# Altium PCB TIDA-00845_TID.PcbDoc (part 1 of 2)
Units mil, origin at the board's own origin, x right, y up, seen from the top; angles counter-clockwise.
Board outline 5936.8 x 4260 mil, 4 copper layers (Top Layer, Layer 2, Layer 3, Bottom Layer), stack 61.2 mil thick; 144 components, 62 nets, 439 pads, 261 vias.
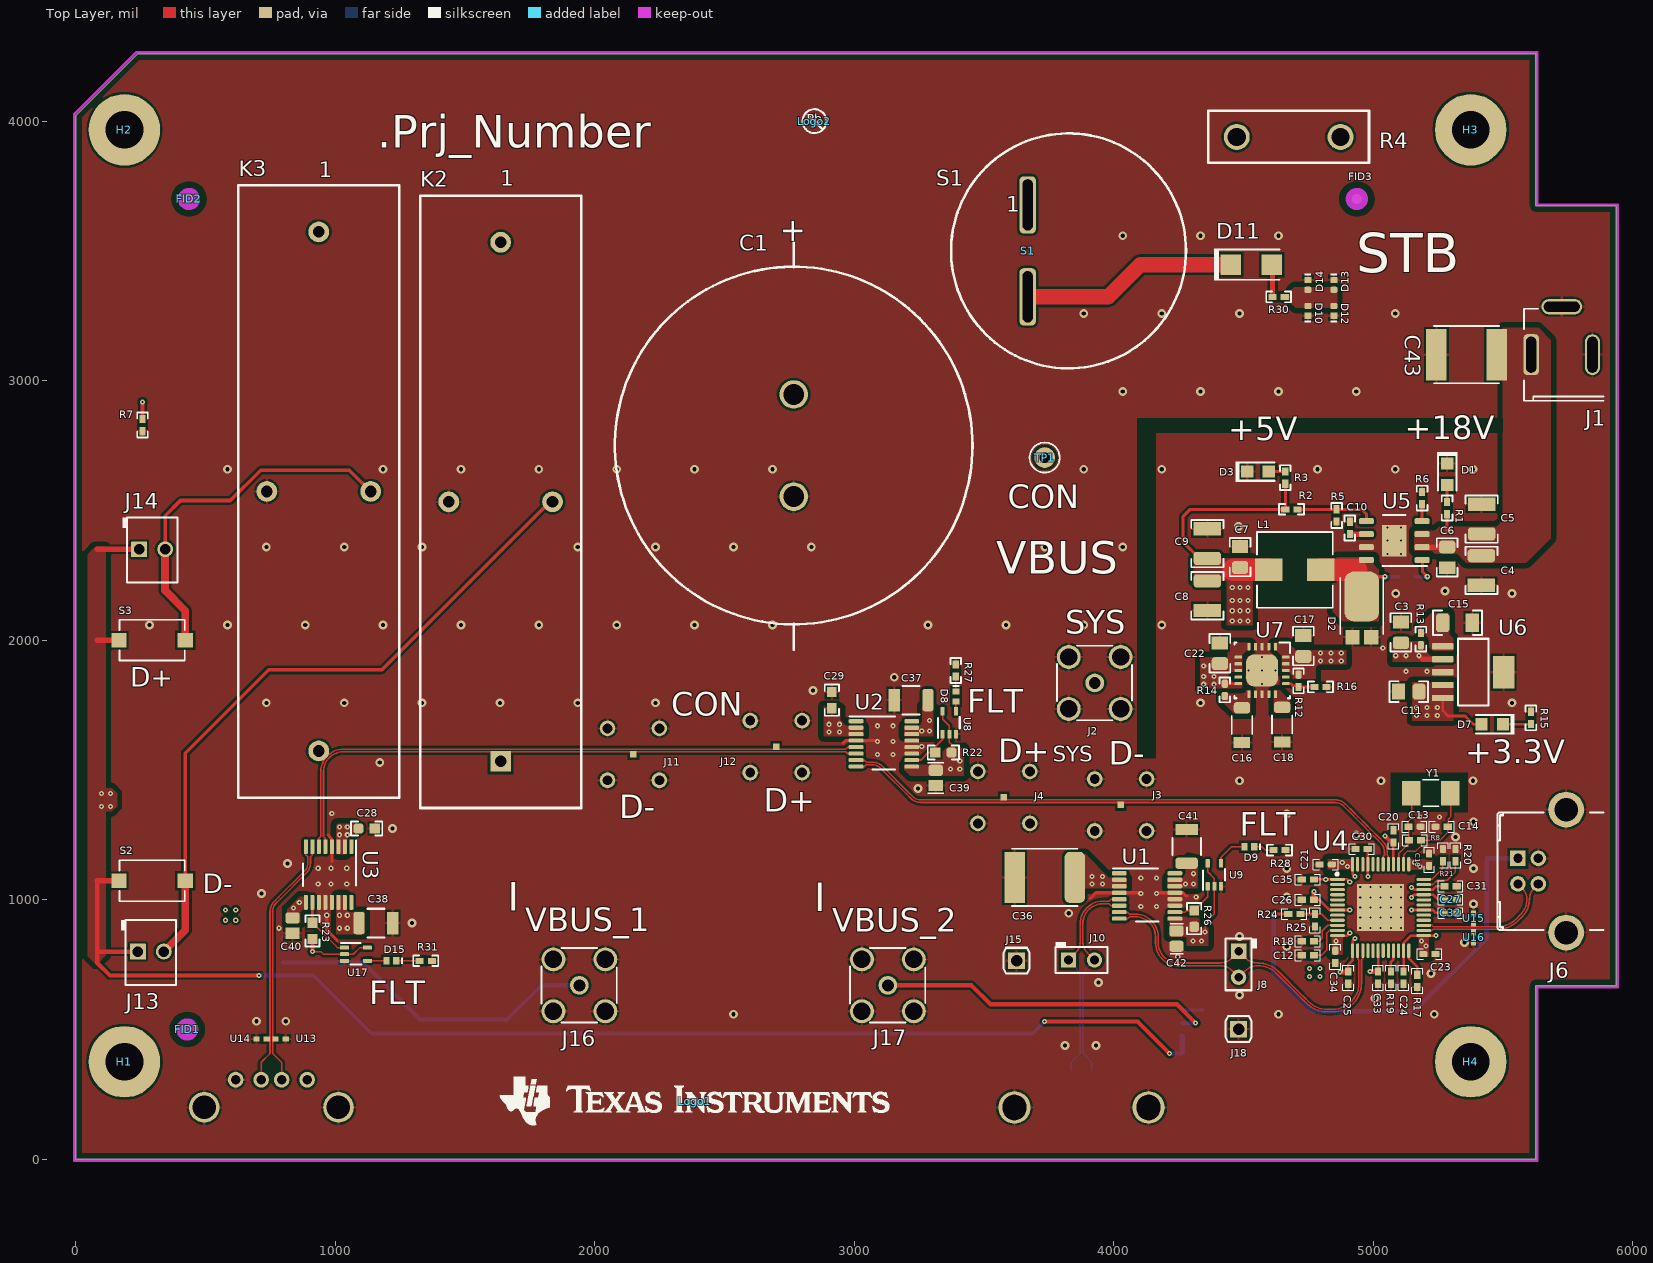
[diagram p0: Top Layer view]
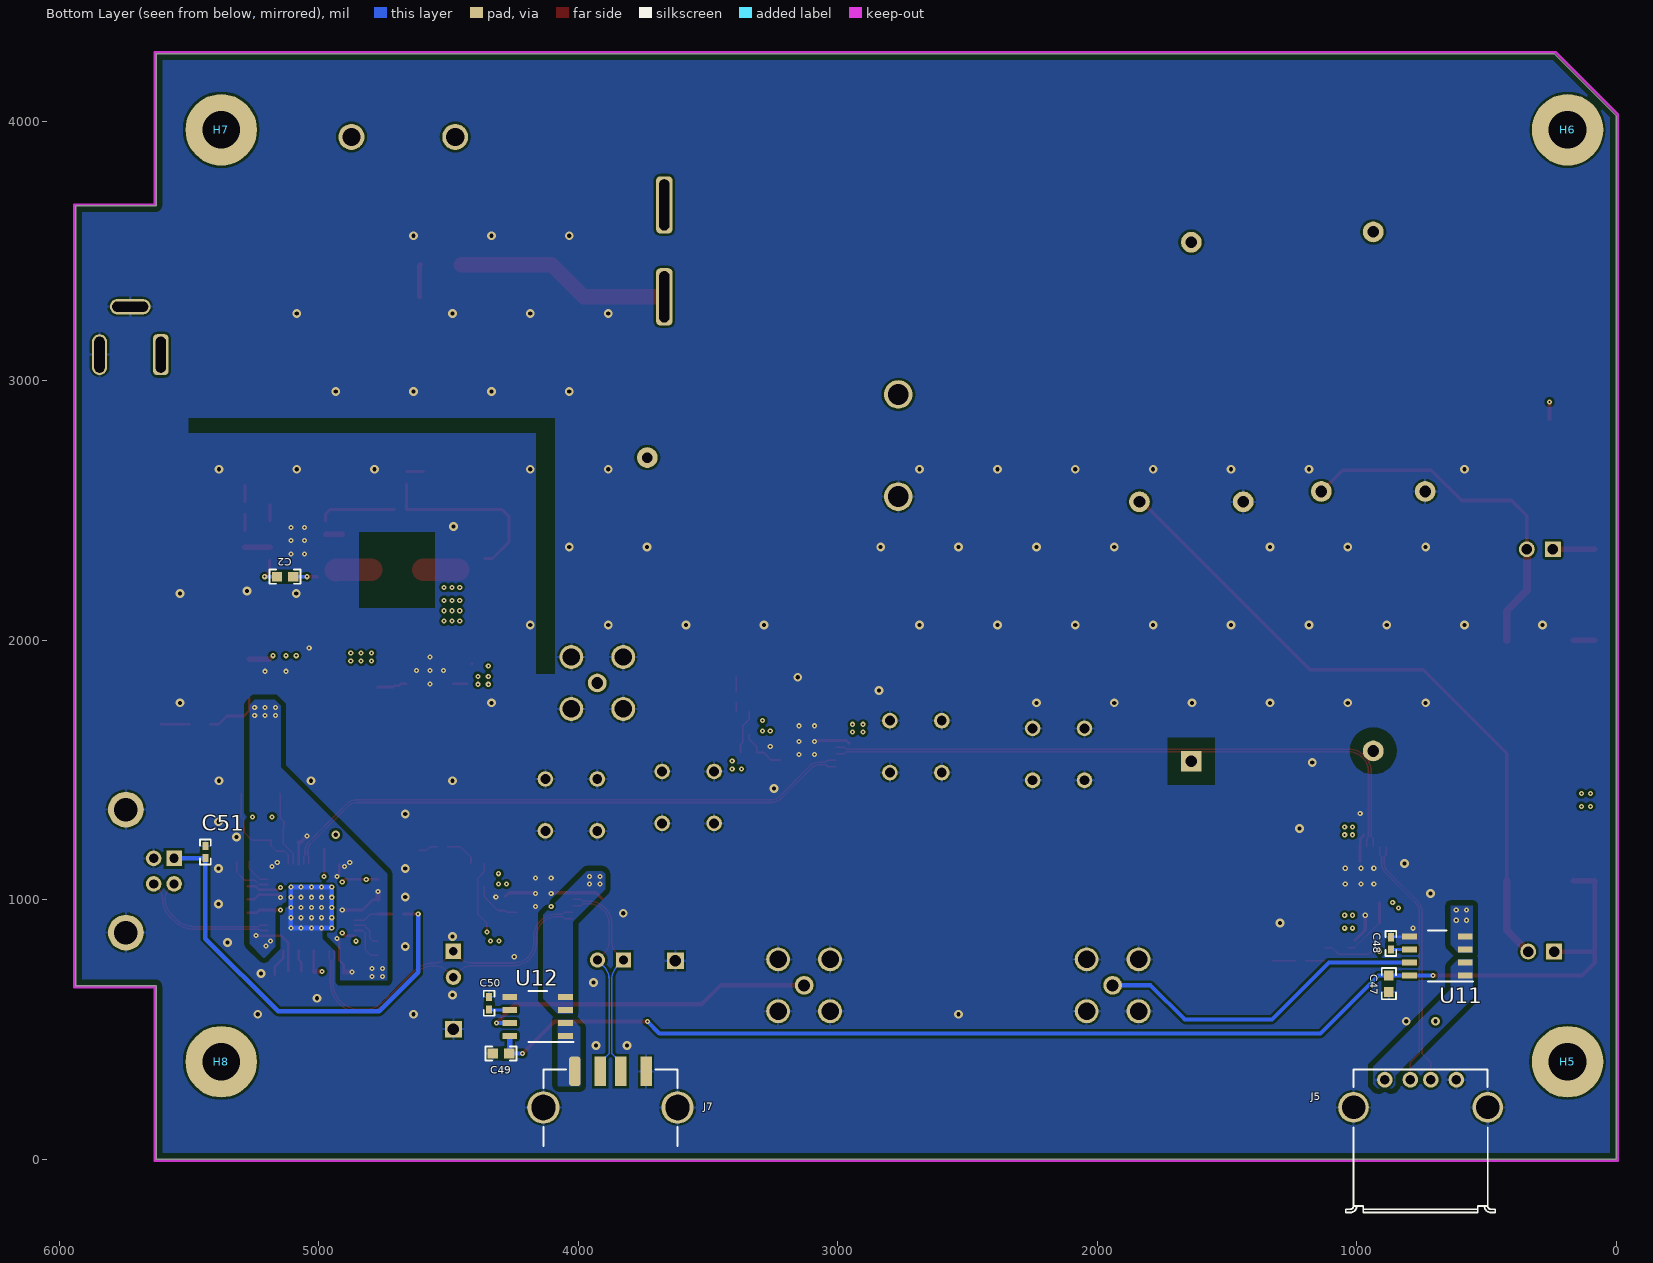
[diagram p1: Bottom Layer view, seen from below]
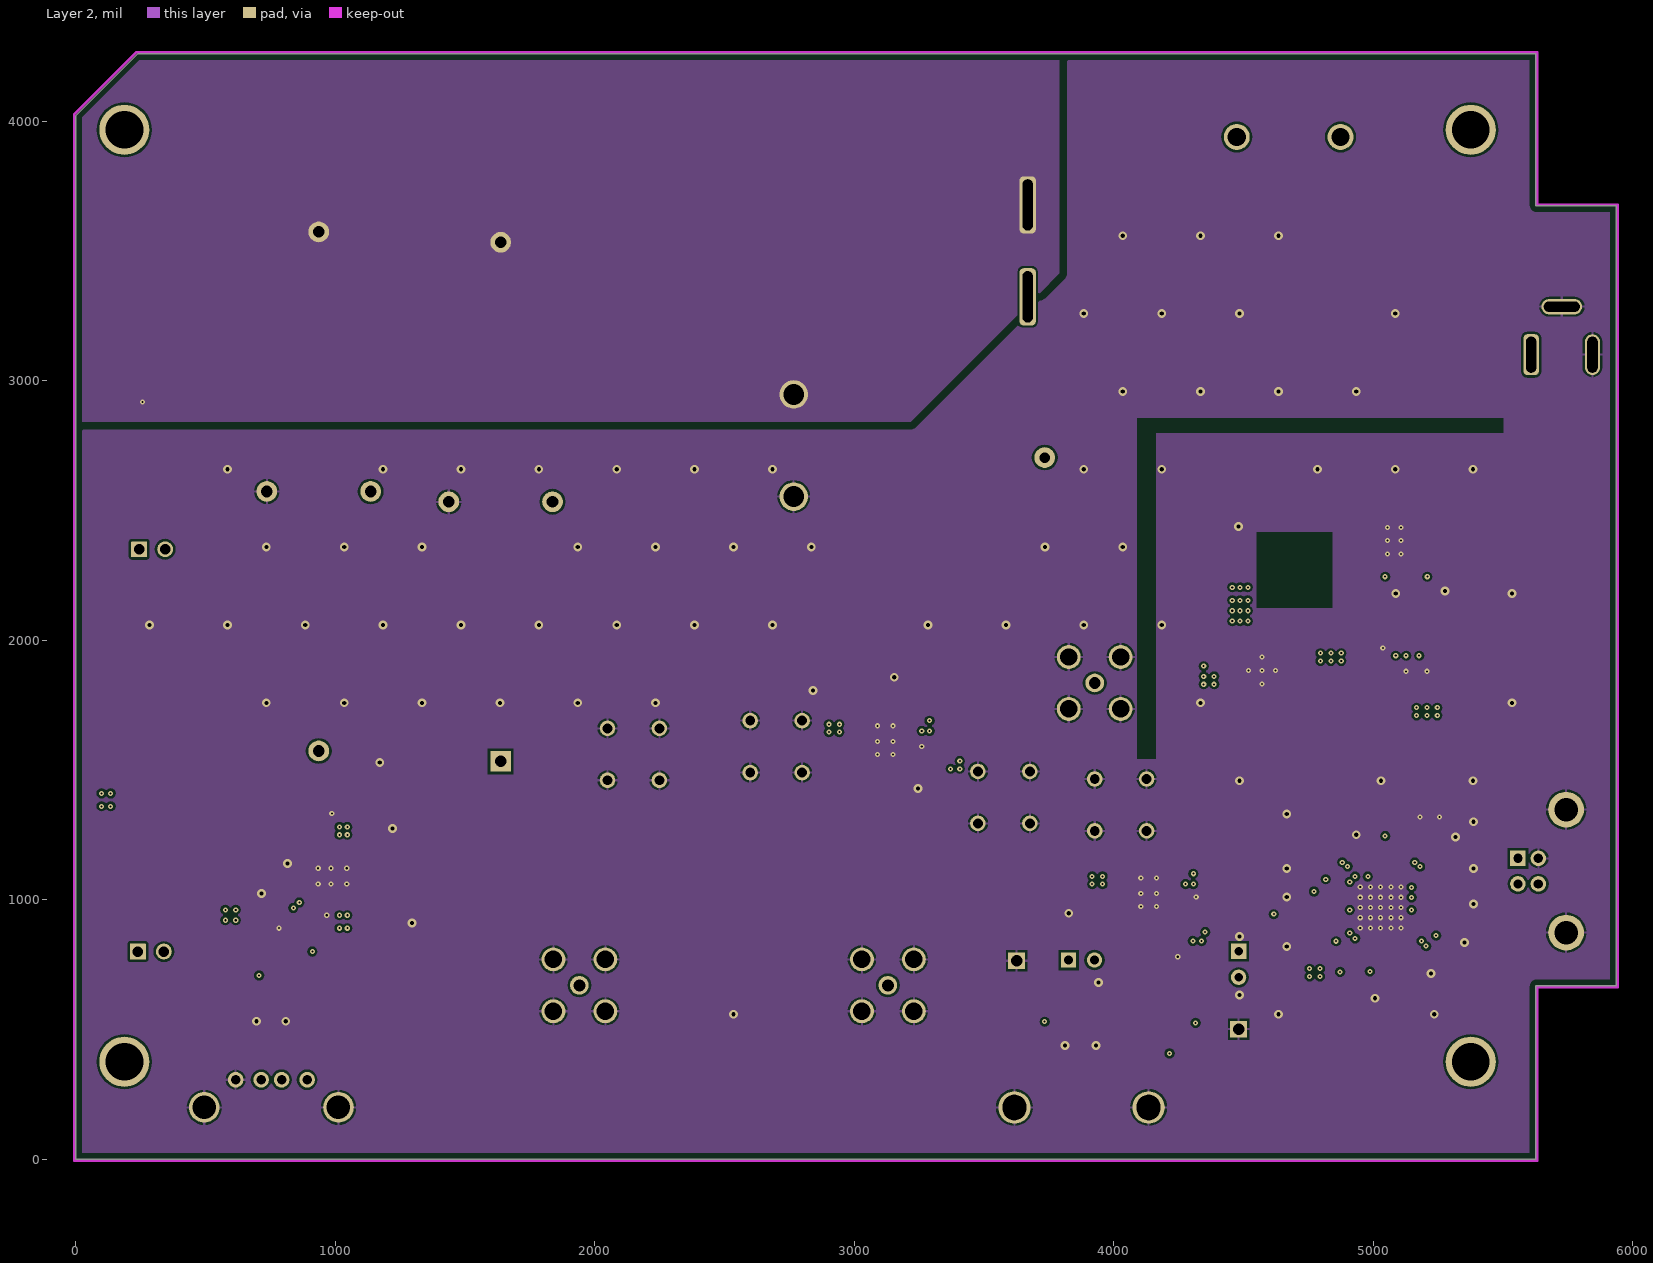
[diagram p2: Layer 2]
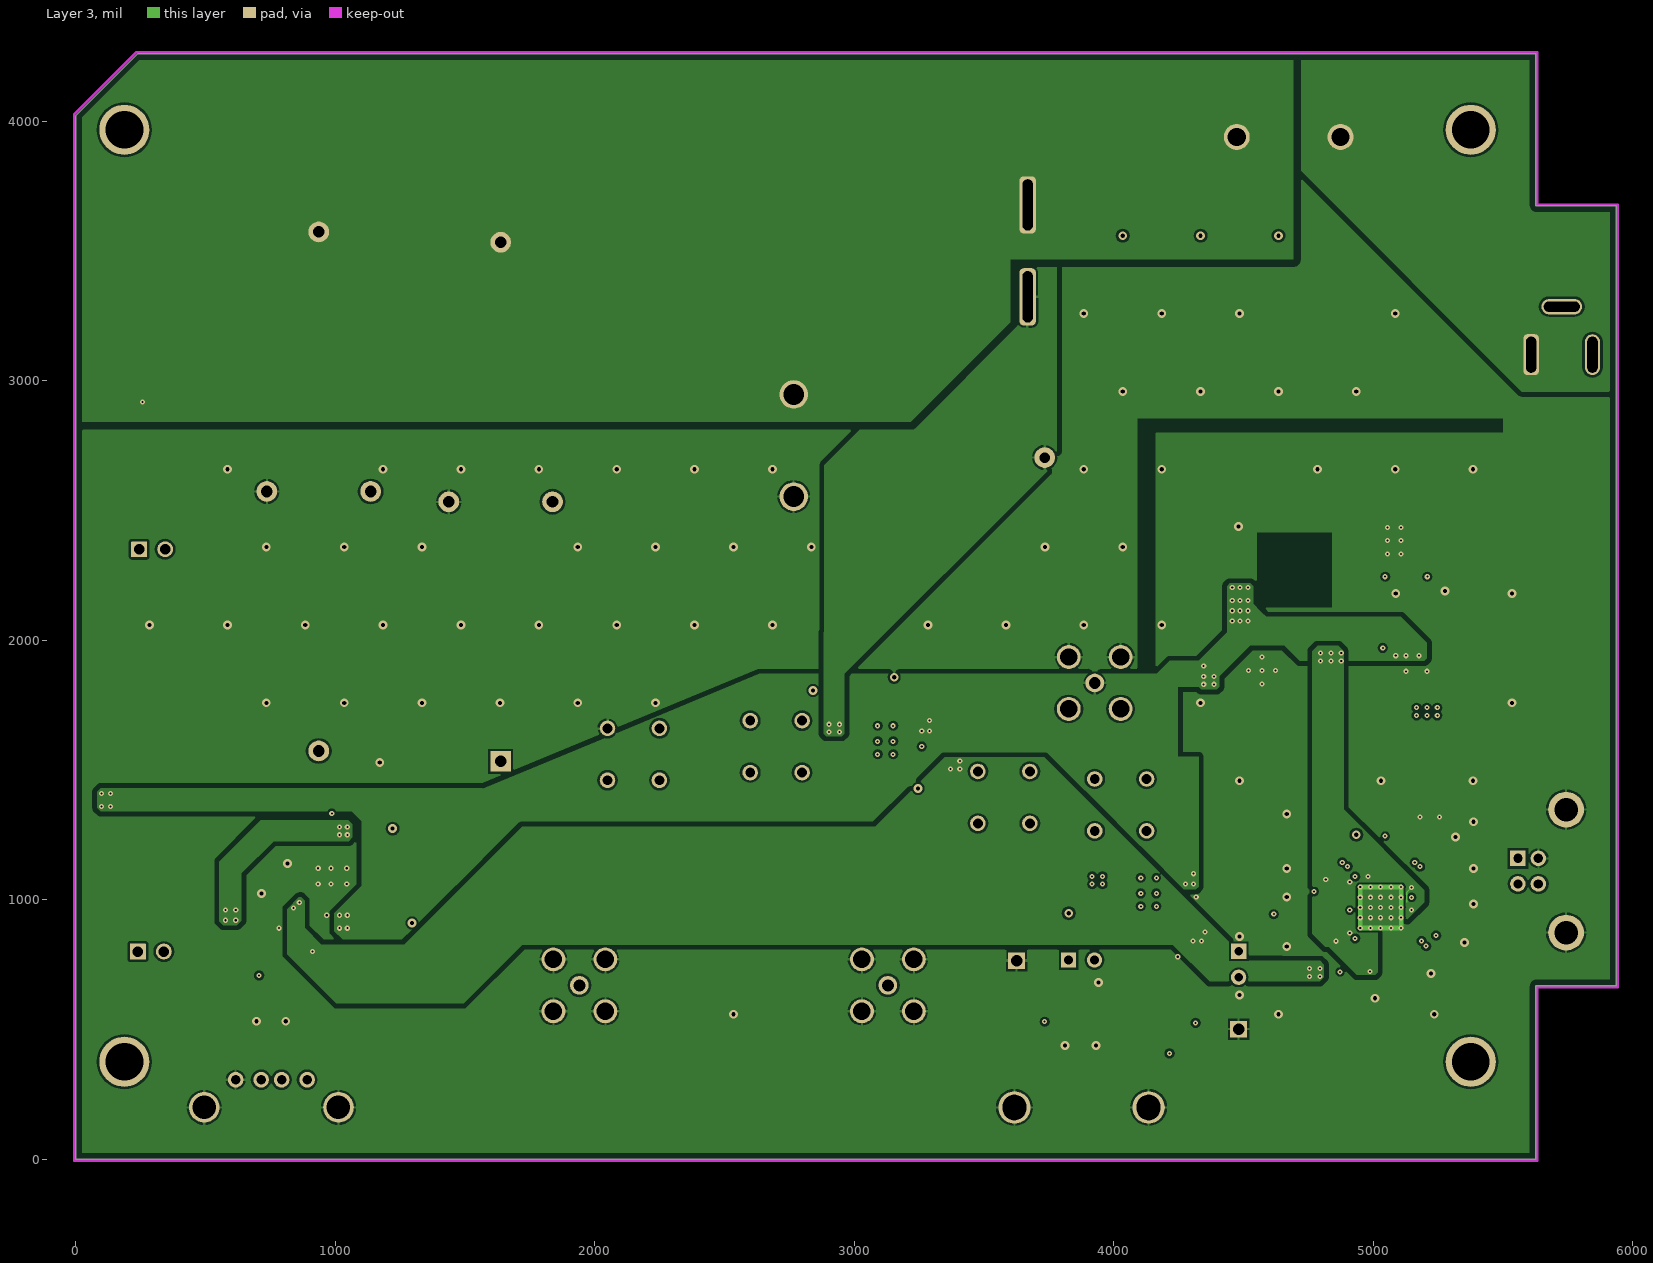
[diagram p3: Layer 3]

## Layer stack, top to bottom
Top Solder: solder mask 0.4, Solder Resist, Dk 3.5
Top Layer: signal copper 1.417
Dielectric1: core 4.5, FR408HR, Dk 3.6
Layer 2: signal copper 1.417
Dielectric 2: prepreg 46.532, FR4, Dk 4.6
Layer 3: signal copper 1.417
Dielectric 3: core 4.5, FR408HR, Dk 3.6
Bottom Layer: signal copper 1.417
Bottom Solder: solder mask 0.4, Solder Resist, Dk 3.5

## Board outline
0,0 0,4020 240,4260 5626.8,4260 5626.8,3673.5 5936.8,3673.5 5936.8,668.5 5626.8,668.5 5626.8,0

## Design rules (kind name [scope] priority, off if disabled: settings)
AcuteAngle [All] p1: minimum=4.50000000000000E+0001 checktracksonly=FALSE
AssemblyTestPointUsage [All] p1: valid=2
Clearance "Stitching GND" [IsStitchingVia and InNet('GND') vs (IsVia and (Not IsStitchingVia)) Or IsPad] p1: gap=5
Clearance Clearance_Poly_Star [InPolygonClass('Star')] p2: gap=0
Clearance Clearance_Keepouts [((IsTrack Or IsArc) And Not InPoly) And IsFree and IsKeepOut vs ((IsTrack Or IsArc) And Not InPoly) And IsFree and IsKeepOut] p3: gap=0
Clearance Clearance_BoardEdge_MountingHoles [OnCopper and InComponentClass('Mounting Holes') vs IsKeepOut] p4: gap=40
Clearance Clearance_BoardEdge_Poly [OnCopper and InPoly vs IsKeepOut] p5: gap=25
Clearance Clearance_BoardEdge [OnCopper and Not InComponentClass('Logo') and not InComponentClass('FiducialMark') and not InRegion(1000,500,4000,800) and Not IsKeepout vs IsKeepOut] p6: gap=62
Clearance Clearance_Poly_to_Kx.2_Low_Cap [InPolygon and OnBottomLayer and not InPolygonClass('Star') vs InPadClass('Low_Cap')] p7: gap=50
Clearance Clearance_Poly_to_Poly_Cap [InPolygon and InNet('NetC1_1') and not InPolygonClass('Star') vs InPolygon] p8: gap=30
Clearance Clearance_Poly_to_Poly [InPolygon and not InPolygonClass('Star') vs InPolygon] p9: gap=20
Clearance Clearance_Poly [InPolygon and not InPolygonClass('Star')] p10: gap=9
Clearance [All] p11: gap=3.93
ComponentClearance ComponentClearance_BigCap [InComponentClass('BigCap')] p1: gap=0 collisioncheckmode=3 verticalgap=0 showdistances=FALSE
ComponentClearance ComponentClearance_MountingHoles_FiducialMarks [InComponentClass('Mounting Holes') vs InComponentClass('FiducialMark')] p2: gap=50 collisioncheckmode=3 verticalgap=11.3 showdistances=FALSE
ComponentClearance ComponentClearance_Shunt [InComponentClass('Header') vs InComponentClass('Shunt')] p3: gap=0 collisioncheckmode=3 verticalgap=0 showdistances=FALSE
ComponentClearance ComponentClearance_Logo [InComponentClass('Logo')] p4: gap=50 collisioncheckmode=3 verticalgap=11.2 showdistances=FALSE
ComponentClearance ComponentClearance_ScrewToNut [(HasFootprint('NY PMS 440 0025 PH')) vs (HasFootprint('Keystone_1902C'))] p5: gap=5 collisioncheckmode=3 verticalgap=11.1 showdistances=FALSE
ComponentClearance ComponentClearance_MountingHoles [InComponentClass('Mounting Holes')] p6: gap=250 collisioncheckmode=3 verticalgap=100000 showdistances=FALSE
ComponentClearance ComponentClearance_SmallPassives [HasFootprint('0201*') or HasFootprint('0402*') or HasFootprint('0508') or HasFootprint('0603*') or HasFootprint('0612') or HasFootprint('0805*') or HasFootprint('0815*') or HasFootprint('0830*') or HasFootprint('1206*') or HasFootprint('1210*') or HasFootprint('1808*') or HasFootprint('1812*') or HasFootprint('1825*') or HasFootprint('2010*') or HasFootprint('2220*') or HasFootprint('2225*') or HasFootprint('2512*') or HasFootprint('2728*') or HasFootprint('3518*') vs HasFootprint('0201*') or HasFootprint('0402*') or HasFootprint('0508') or HasFootprint('0603*') or HasFootprint('0612') or HasFootprint('0805*') or HasFootprint('0815*') or HasFootprint('0830*') or HasFootprint('1206*') or HasFootprint('1210*') or HasFootprint('1808*') or HasFootprint('1812*') or HasFootprint('1825*') or HasFootprint('2010*') or HasFootprint('2220*') or HasFootprint('2225*') or HasFootprint('2512*') or HasFootprint('2728*') or HasFootprint('3518*')] p7: gap=20 collisioncheckmode=3 verticalgap=11 showdistances=FALSE
ComponentClearance ComponentClearance_THtoSMT [IsThruComponent vs IsSMTComponent] p8: gap=76 collisioncheckmode=3 verticalgap=30 showdistances=FALSE
ComponentClearance ComponentClearance_THtoTH [IsThruComponent or not (InComponentClass('BigCap') and InComponentClass('BigResistor')) vs IsThruComponent] p9: gap=63 collisioncheckmode=3 verticalgap=30 showdistances=FALSE
ComponentClearance [All] p10: gap=9 collisioncheckmode=3 verticalgap=9 showdistances=FALSE
DiffPairsRouting [All] p1: maxlimit=4.01 minlimit=3.99 mostfreqgap=4 toplayer_minwidth=6.24 toplayer_maxwidth=6.26 toplayer_prefwidth=6.25 midlayer1_minwidth=6.24 midlayer1_maxwidth=6.26 midlayer1_prefwidth=6.25 midlayer2_minwidth=6.24 midlayer2_maxwidth=6.26 midlayer2_prefwidth=6.25 bottomlayer_minwidth=6.24 bottomlayer_maxwidth=6.26 bottomlayer_prefwidth=6.25 maxuncoupledlength=1000
FabricationTestPointUsage TestPointUsage [All] p1: valid=2 allowmultiple=FALSE
FabricationTestpoint Testpoint [All] p1: side=3 testpointundercomponent=TRUE minsize=40 maxsize=100 preferedsize=60 minholesize=0 maxholesize=40 preferedholesize=32 testpointgrid=1 allowsidetop=TRUE allowsidebottom=TRUE usegrid=TRUE gridtolerance=0.01
FanoutControl Fanout_LCC [IsLCC] p1: bgadir=Out bgaviamode=Centered fanoutstyle=Auto fanoutdirection=Alternating viagrid=1 // Fanout_LCC (Default Rule)
FanoutControl Fanout_BGA [IsBGA] p2: bgadir=Out bgaviamode=Centered fanoutstyle=Auto fanoutdirection=Alternating viagrid=1 // Fanout_BGA (Default Rule)
FanoutControl Fanout_Default [All] p4: bgadir=Out bgaviamode=Centered fanoutstyle=Auto fanoutdirection=Alternating viagrid=1 // Fanout_Default (Default Rule)
FanoutControl Fanout_Small [(CompPinCount < 5)] p5: bgadir=Out bgaviamode=Centered fanoutstyle=Auto fanoutdirection=OutThenIn viagrid=1 // Fanout_Small (Default Rule)
HoleSize [All] p1: absolutevalues=TRUE maxlimit=251 minlimit=7.87 maxpercent=80.000 minpercent=20.000
MinimumAnnularRing MinimumAnnularRing_ThermalPadVias [IsVia and InAnyComponent] p1: minimumring=5.91
MinimumAnnularRing [All] p2: minimumring=5.9
MinimumSolderMaskSliver MinimumSolderMaskSliver_Logo [InComponentClass('Logo') vs InComponentClass('Logo')] p1: minsoldermaskwidth=0.7
MinimumSolderMaskSliver [All] p2: minsoldermaskwidth=3.94
PlaneConnect [All] p1: planeconnectstyle=Relief reliefexpansion=10 reliefentries=4 reliefconductorwidth=10 reliefairgap=10
PolygonConnect PolygonConnect_PowerPad [InPadClass('PowerPad')] p1: connectstyle=Direct reliefconductorwidth=10 reliefentries=4 polygonreliefangle="90 Angle" airgapwidth=8
PolygonConnect PolygonConnect_Rounded_Rect [IsRoundedRectangularPad] p2: connectstyle=Direct reliefconductorwidth=10 reliefentries=4 polygonreliefangle="90 Angle" airgapwidth=10
PolygonConnect PolygonConnect_VBUS1_CON [InNet('VBUS1_CON') or InNet('VBUS1_CONA') or InNet('NetC29_1')  or InNet('NetC1_1')] p3: connectstyle=Direct reliefconductorwidth=10 reliefentries=4 polygonreliefangle="90 Angle" airgapwidth=10
PolygonConnect PolygonConnect_18V [InNet('+18V')] p4: connectstyle=Direct reliefconductorwidth=10 reliefentries=4 polygonreliefangle="90 Angle" airgapwidth=10
PolygonConnect PolygonConnect_VIA [IsVia] p5: connectstyle=Direct reliefconductorwidth=10 reliefentries=4 polygonreliefangle="90 Angle" airgapwidth=10
PolygonConnect [not IsVia] p6: connectstyle=Relief reliefconductorwidth=10 reliefentries=4 polygonreliefangle="90 Angle" airgapwidth=8
RoutingVias ThermalPadVias [IsVia and InAnyComponent] p1: holewidth=7.87 width=19.68 viastyle="Through Hole" minholewidth=7.87 minwidth=19.68 maxholewidth=12.99 maxwidth=23.62
RoutingVias [All] p2: holewidth=16 width=34 viastyle="Through Hole" minholewidth=7.87 minwidth=19.6 maxholewidth=40 maxwidth=65
ShortCircuit ShortCircuit_1 [InPolygonClass('Star') vs InNet('AGND') and InNet('DGND')] p2: allowed=TRUE
SilkToBoardRegionClearance [Not ((IsComment or IsDesignator) And (Hide <> 'False')) and not InRegion(1000,500,4000,800)] p1:
SilkToSilkClearance SilkToSilkClearance_Pb-FreeLogo [(HasFootprint('Pb-Free_Overlay_Medium') OR HasFootprint('Pb-Free_Overlay_Small')) vs (HasFootprint('Pb-Free_Overlay_Medium') OR HasFootprint('Pb-Free_Overlay_Small'))] p1: silktosilkclearance=0
SilkToSilkClearance [All] p2: silktosilkclearance=4
SilkToSolderMaskClearance SilkToComonentPadClearance [IsPad and InAnycomponent] p1: minsilkscreentomaskgap=3.79 clearancetoexposedcopper=TRUE
SilkToSolderMaskClearance "Silk to Solder Mask Opening" [All] p2: minsilkscreentomaskgap=4 clearancetoexposedcopper=FALSE
SolderMaskExpansion [All] p1: expansion=1.97
UnpouredPolygon [All] p1: allowunpoured=FALSE
Width [All] p1: maxlimit=100 minlimit=4 preferedwidth=30 checkconnectedcopper=TRUE
14 further rules are at their usual default settings.

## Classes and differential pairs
pad class Low_Cap: K2-2 K3-2
component class BigResistor: R4
component class BigCap: C1
component class Sheet1: C1 C2 C3 C4 C5 C6 C7 C8 C9 C10 C11 C12 C13 C14 C15 C16 C17 C18 C19 C20 C21 C22 C23 C24 C25 C26 C27 C28 C29 C30 C31 C32 C33 C34 C35 C36 C37 C38 C39 C40 C41 C42 C43 C47 C48 C49 C50 C51 D1 D2 D3 D7 D8 D9 D10 D11 D12 D13 D14 D15 J1 J2 J3 J4 J5 J6 J7 J8 J10 J11 J12 J13 J14 J15 J16 J17 J18 K2 K3 L1 R1 R2 R3 R4 R5 R6 R7 R8 R12 R13 R14 R15 R16 R17 R18 R19 R20 R21 R22 R23 R24 R25 R26 R27 R28 R30 R31 S1 S2 S3 TP1 U1 U2 U3 U4 U5 U6 U7 U8 U9 U11 U12 U13 U14 U15 U16 U17 Y1
component class IsEdgeConnector: J1 J6 J7
component class AssemblyNote: ZZ1 ZZ2 ZZ3
component class FiducialMark: FID1 FID2 FID3
component class TIDA-0085_TID_Hardware: FID1 FID2 FID3 H1 H2 H3 H4 H5 H6 H7 H8 Logo1 Logo2 ZZ1 ZZ2 ZZ3
component class Logo: Logo1
pad class PowerPad: U4-1 U4-12 U4-25 U4-37 U4-48
component class Header: J8 J10 J15 J18
differential pair DP1_STB: +DP1_STB_P -DP1_STB_N
differential pair DP1_SYS: +DP1_SYS_P -DP1_SYS_N
differential pair DP2_CON: +DP2_CON_P -DP2_CON_N
differential pair DP2_SYS: +DP2_SYS_P -DP2_SYS_N
differential pair UP: +UP_P -UP_N
differential pair DP1_CON: +DP1_CON_P -DP1_CON_N

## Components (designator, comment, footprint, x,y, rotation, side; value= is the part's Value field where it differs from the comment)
C1 "B41231B5229M" EKMH350VSN223MA50T 2766.8,2946.79 r270 top
C2 "GRM188R71C104KA01D" 0603#1 5129.8,2244.49 r0 bottom
C3 "0805YD106MAT2A" 0805_HV#1 5106.8,2030 r90 top
C4 "GRM32ER71H475KA88L" 1210#1 5416.79,2268.49 r90 top
C5 "GRM32ER71H475KA88L" 1210#1 5417.79,2466.49 r270 top
C6 "GRM21BR71H224KA01L" 0805_HV#2 5284.8,2319 r90 top
C7 "GRM21BR71E105KA99L" 0805_HV#1 4486.8,2320 r90 top
C8 "GRM32ER61C476ME15L" 1210#2 4360.7,2171.2 r270 top
C9 "GRM32ER61C476ME15L" 1210#2 4360.7,2371.94 r90 top
C10 "GRM155R71C223KA01D" 0402#1 4909.79,2432.49 r270 top
C11 "0805YD106MAT2A" 0805_HV#1 5136.8,1802 r180 top
C12 "GRM155R70J105MA12D" 0402#1 4748.17,786.03 r0 top
C13 "GRM1555C1H200JA01D" 0402#2 5158.99,1281.15 r0 top
C14 "GRM1555C1H200JA01D" 0402#2 5263.36,1281.15 r180 top
C15 "C1206C564K5RACTU" 1206 5324.8,2067 r180 top
C16 "202R18W102KV4E" 1206_190 4493.96,1672.39 r90 top
C17 "0805YD106MAT2A" 0805_HV#1 4730.96,1977.39 r90 top
C18 "202R18W102KV4E" 1206_190 4648.96,1674.39 r90 top
C19 "GRM155R71H103KA88D" 0402#3 5215.33,1154 r270 top
C20 "GRM155R71H103KA88D" 0402#1 5077.8,1244 r270 top
C21 "TMK105B7104MV-FR" 0402#2 4816.8,1135.89 r0 top
C22 "0805YD106MAT2A" 0805_HV#1 4408.96,1949.39 r90 top
C23 "TMK105B7104MV-FR" 0402#2 5216.8,790 r180 top
C24 "GRM155R71H103KA88D" 0402#1 5117.18,699.89 r90 top
C25 "TMK105B7104MV-FR" 0402#1 4903.79,699.89 r90 top
C26 "GRM155R71H103KA88D" 0402#1 4748.17,999.89 r0 top
C27 "TMK105B7104MV-FR" 0402#1 5297.85,1001.05 r180 top
C28 "UMK107AB7105KA-T" 0603#2 1121.46,1274.25 r0 top
C29 "UMK107AB7105KA-T" 0603#1 2913.8,1768.86 r90 top
C30 "GRM155R71H103KA88D" 0402#1 4954.97,1195.58 r0 top
C31 "GRM155R71H103KA88D" 0402#1 5297.85,1051.95 r180 top
C32 "GRM155R71H103KA88D" 0402#1 5297.85,949.05 r180 top
C33 "GRM155R71H103KA88D" 0402#1 5018.75,699.89 r90 top
C34 "TMK105B7104MV-FR" 0402#2 4853.79,779.89 r90 top
C35 "TMK105B7104MV-FR" 0402#1 4748.17,1078.16 r0 top
C36 "CKG57NX7R2A106M500JH" CKG57N#1 3734.01,1086 r180 top
C37 "C1210C107M8PACTU" 1210_280 3219.23,1769 r180 top
C38 "C1210C107M8PACTU" 1210_280 1156.8,910 r0 top
C39 "C2012X7R0J106M125AB" 0805L#1 3314.23,1469 r270 top
C40 "C2012X7R0J106M125AB" 0805L#1 835.8,900 r270 top
C41 "C1210C107M8PACTU" 1210_280 4280.8,1205.62 r90 top
C42 "C2012X7R0J106M125AB" 0805L#2 4241.8,850 r270 top
C43 "CKG57NX7R2A106M500JH" CKG57N#2 5359.35,3099.89 r180 top
C47 "06033C104JAT2A" 0603#1 876.5,676.23 r270 bottom
C48 "885012205044" 0402#1 868.96,831.47 r90 bottom
C49 "06033C104JAT2A" 0603#1 4297.76,407.43 r0 bottom
C50 "885012205044" 0402#1 4343.39,600.93 r90 bottom
C51 "JMK105BJ225MV-F" 0402#1 5436.8,1183.75 r90 bottom
D1 "LTST-C171GKT" LED_LTST-C171 5284.8,2639 r90 top
D2 "PDS560-13" PowerDI5 4955.8,2090 r90 top
D3 "LTST-C171GKT" LED_LTST-C171 4555.83,2649.64 r180 top
D7 "LTST-C171GKT" LED_LTST-C171 5458.45,1675.86 r0 top
D8 "VLMS1500-GS08" VLMx1500_Red#1 3392.02,1783 r90 top
D9 "VLMS1500-GS08" VLMx1500_Red#1 4523.01,1204.21 r0 top
D10 "VLMS1500-GS08" VLMx1500_Red#2 4748.18,3268.74 r270 top
D11 "1SMA5929BT3G" SMA 4529.61,3447.15 r0 top
D12 "VLMS1500-GS08" VLMx1500_Red#2 4848.18,3268.74 r270 top
D13 "VLMS1500-GS08" VLMx1500_Red#2 4848.18,3368.8 r90 top
D14 "VLMS1500-GS08" VLMx1500_Red#2 4748.18,3368.8 r90 top
D15 "VLMS1500-GS08" VLMx1500_Red#1 1216.8,764.41 r0 top
FID1 "Fiducial" Fiducial10-20 430,500 r90 top
FID2 "Fiducial" Fiducial10-20 436.8,3700 r90 top
FID3 "Fiducial" Fiducial10-20 4936.8,3700 r90 top
H1 "29311" Keystone29311#1 187.8,375.5 r90 top
H2 "29311" Keystone29311#2 187.8,3966.5 r90 top
H3 "29311" Keystone29311#1 5375.8,3966.5 r90 top
H4 "29311" Keystone29311#1 5375.8,375.5 r90 top
H5 "R30-3000502" Harwin_R30-3000502 187.8,375.5 r90 bottom
H6 "R30-3000502" Harwin_R30-3000502 187.8,3966.5 r90 bottom
H7 "R30-3000502" Harwin_R30-3000502 5375.8,3966.5 r90 bottom
H8 "R30-3000502" Harwin_R30-3000502 5375.8,375.5 r90 bottom
J1 "PJ-202AH" CONN_CUI-PJ-202AH 5608.42,3100 r0 top
J2 "131-3701-261" CONN_131-3701-261 3926.8,1835 r0 top
J3 "131-5031-00" Tek_131-5031-00 4026.8,1365 r0 top
J4 "131-5031-00" Tek_131-5031-00 3576.8,1394 r90 top
J5 "292303-4" CONN_TE_292303-4 754.2,306.19 r180 bottom
J6 "67068-8000" MOLEX_67068-8000 5743.07,1109.89 r0 top
J7 "896-43-004-00-000000" CONN_USB_896-43-004-00-000000 3875.92,269.09 r180 bottom
J8 "800-10-002-10-001000" Mill-Max_800-10-002-10-001000 4481.36,750.93 r270 top
J10 "800-10-002-10-001000" Mill-Max_800-10-002-10-001000 3875.92,767.5 r0 top
J11 "131-5031-00" Tek_131-5031-00 2149.49,1560.23 r0 top
J12 "131-5031-00" Tek_131-5031-00 2699.29,1589.75 r0 top
J13 "22-23-2021" Molex_22-23-2021 290,800 r0 top
J14 "22-23-2021" Molex_22-23-2021 294.8,2350 r0 top
J15 "61300111121" WURTH_61300111121 3625.92,764.71 r0 top
J16 "131-3701-261" CONN_131-3701-261 1941.05,670 r0 top
J17 "131-3701-261" CONN_131-3701-261 3129.74,670 r0 top
J18 "61300111121" WURTH_61300111121 4481.36,500.93 r0 top
K2 "DAR70510" DAR70510#1 1637.8,3533.11 r270 top
K3 "DAR70510" DAR70510#2 936.73,3573.07 r270 top
L1 "744314650" WE-HCI_7050 4697.8,2271 r180 top
Logo1 "Texas Instruments" TI_Horizontal_Overlay_Medium 2384.8,223.64 r0 top
Logo2 "Pb-Free Symbol" Pb-Free_Overlay_Small 2846.8,4000 r0 top
R1 "CRCW0402825RFKED" 0402#1 5284.8,2509 r270 top
R2 "CRCW0402100KDHEDP" 0402#1 4684.8,2504.11 r0 top
R3 "CRCW0402255RFKED" 0402#1 4661.17,2626.02 r90 top
R4 "TEH100M7R50FE" TEH100M7R50FE 4874.11,3939 r180 top
R5 "CRCW040217K8FKED" 0402#1 4858.79,2480.49 r270 top
R6 "CRCW040249K9FKED" 0402#1 5188.07,2547 r90 top
R7 "CRCW040230K1FKED" 0402#1 257.6,2828.74 r90 top
R8 "CRCW04021M00FKED" 0402#1 5160.81,1229.21 r0 top
R12 "CRCW04021K87FKED" 0402#2 4711.96,1843.39 r90 top
R13 "CRCW040230R1FKED" 0402#2 5183.8,2004 r270 top
R14 "CRCW040230R1FKED" 0402#3 4427.94,1808.39 r90 top
R15 "CRCW0402330RJNED" 0402#1 5607.51,1700.62 r270 top
R16 "CRCW04024K99FKED" 0402#1 4796.74,1819.76 r180 top
R17 "CRCW04029K53FKED" 0402#1 5169.8,687.32 r270 top
R18 "CRCW04021K00FKED" 0402#1 4748.17,839.89 r180 top
R19 "CRCW04024K70JNED" 0402#1 5067.96,699.89 r90 top
R20 "CRCW04024K70JNED" 0402#4 5316.59,1171.95 r270 top
R21 "CRCW04024K70JNED" 0402#4 5268.59,1171.95 r270 top
R22 "CRCW060310K0FKEA" 0603#3 3343.39,1567.05 r0 top
R23 "CRCW060310K0FKEA" 0603#1 912.8,880 r90 top
R24 "CRCW040290K9FKED" 0402#1 4696.17,944.3 r0 top
R25 "CRCW040210K0DHEDP" 0402#1 4776.17,920.68 r90 top
R26 "CRCW060310K0FKEA" 0603#3 4309.8,927 r270 top
R27 "CRCW0402165RFKED" 0402#1 3391.45,1883 r90 top
R28 "CRCW0402165RFKED" 0402#1 4638.8,1191 r0 top
R30 "CRCW0402255RFKED" 0402#1 4635.58,3322.83 r0 top
R31 "CRCW0402165RFKED" 0402#1 1349.11,764.41 r0 top
S1 "GPB527C202BR" GPB527C202BR 3825.92,3500 r0 top
S2 "KSR221GLFS" KSR 294.8,1073 r180 top
S3 "KSR221GLFS" KSR 294.8,2000 r180 top
TP1 "5000" Keystone5000 3734.02,2703.52 r0 top
U1 "TPD3S714QDBQRQ1" DBQ0016A_N 4128.39,1014.24 r0 top
U2 "TPD3S714QDBQRQ1" DBQ0016A_N 3114.39,1600.11 r0 top
U3 "TPD3S714QDBQRQ1" DBQ0016A_N 974.81,1096.93 r270 top
U4 "TUSB4020BIPHP" PHP0048C_N 5028.59,969.89 r0 top
U5 "LMR14030SDDAR" DDA0008E_N 5080.79,2383.49 r180 top
U6 "TPS7A4533DCQR" DCQ0006A_N 5384.98,1876.5 r0 top
U7 "TPS74801RGWR" RGW0020A 4571.96,1883.39 r270 top
U8 "SN74LVC1G125" DCK0005A_N 3366.43,1681.98 r90 top
U9 "SN74LVC1G125" DCK0005A_N 4387.8,1095.54 r90 top
U11 "ACS712ELCTR-05B-T" SOIC-8 689.64,782.89 r0 bottom
U12 "ACS712ELCTR-05B-T" SOIC-8 4156.8,550 r0 bottom
U13 "TPD1E05U06DPYR" DPY0002A 789.8,463.78 r0 top
U14 "TPD1E05U06DPYR" DPY0002A 716.8,463.78 r180 top
U15 "TPD1E05U06DPYR" DPY0002A 5386.85,927.5 r90 top
U16 "TPD1E05U06DPYR" DPY0002A 5386.87,855 r270 top
U17 "SN74LVC1G125" DCK0005A_N 1080.13,790 r0 top
Y1 "445C25D24M00000" 445C25D24M00000 5146.8,1410 r0 top
ZZ1 "These assemblies are ESD sensitive, ESD precautions shall be observed." AssemblyNote 6539.61,3988.28 r0 top
ZZ2 "These assemblies must be clean and free from flux and all contaminants. Use of no clean flux is not acceptable." AssemblyNote 6539.61,4230.82 r0 top
ZZ3 "These assemblies must comply with workmanship standards IPC-A-610 Class 2, unless otherwise specified." AssemblyNote 6537.4,4374.14 r0 top

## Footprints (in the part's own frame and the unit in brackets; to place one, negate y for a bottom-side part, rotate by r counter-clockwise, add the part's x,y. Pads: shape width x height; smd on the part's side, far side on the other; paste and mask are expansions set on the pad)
0402#1 [mm] "0402 from SM-752 data"
  rect 0.8x0.6 smd: 1(-0.6,0) 2(0.6,0)
  silkscreen extent -1.22,-0.52 1.22,0.52, body extent -0.55,-0.3 0.55,0.3, height 0.6
0402#2 [mm] "0402 from SM-752 data"
  rect 0.8x0.6 smd: 1(-0.6,0)
  rrect50% 0.8x0.6 smd: 2(0.6,0)
  silkscreen extent -1.22,-0.52 1.22,0.52, body extent -0.55,-0.3 0.55,0.3, height 0.6
0402#3 [mm] "0402 from SM-752 data"
  rrect50% 0.8x0.6 smd: 1(-0.6,0) 2(0.6,0)
  silkscreen extent -1.22,-0.52 1.22,0.52, body extent -0.55,-0.3 0.55,0.3, height 0.6
0402#4 [mm] "0402 from SM-752 data"
  rrect50% 0.8x0.6 smd: 1(-0.6,0)
  rect 0.8x0.6 smd: 2(0.6,0)
  silkscreen extent -1.22,-0.52 1.22,0.52, body extent -0.55,-0.3 0.55,0.3, height 0.6
445C25D24M00000 [mm] "CTS 445C25D24M00000"
  rect 1.8x2.4 smd: 1(0,0) 2(3.8,0)
0603#1 [mm] "0603 from SM-752 data"
  rect 1x0.95 smd: 1(-0.8,0) 2(0.8,0)
  silkscreen extent -1.52,-0.69 1.52,0.69, body extent -0.87,-0.47 0.87,0.47, height 1
0603#2 [mm] "0603 from SM-752 data"
  rrect50% 1x0.95 smd: 1(-0.8,0)
  rect 1x0.95 smd: 2(0.8,0)
  silkscreen extent -1.52,-0.69 1.52,0.69, body extent -0.87,-0.47 0.87,0.47, height 1
0603#3 [mm] "0603 from SM-752 data"
  rect 1x0.95 smd: 1(-0.8,0)
  rrect50% 1x0.95 smd: 2(0.8,0)
  silkscreen extent -1.52,-0.69 1.52,0.69, body extent -0.87,-0.47 0.87,0.47, height 1
0805_HV#1 [mil] "0805 with 30mil clearance between pads"
  rrect50% 50x63 smd: 1(-40,0)
  rect 50x63 smd: 2(40,0)
  silkscreen extent -74,-40 74,40, body extent -43,-29 43,29, height 57
0805_HV#2 [mil] "0805 with 30mil clearance between pads"
  rect 50x63 smd: 1(-40,0)
  rrect50% 50x63 smd: 2(40,0)
  silkscreen extent -74,-40 74,40, body extent -43,-29 43,29, height 57
0805L#1 [mm] "0805 from SM-752 data"
  rrect50% 1.1x1.4 smd: 1(-0.75,0)
  rect 1.1x1.4 smd: 2(0.75,0)
  body extent -1.1,-0.72 1.1,0.72, height 1.45
0805L#2 [mm] "0805 from SM-752 data"
  rrect50% 1.1x1.4 smd: 1(-0.75,0) 2(0.75,0)
  body extent -1.1,-0.72 1.1,0.72, height 1.45
1206 [mm] "1206 from SM-752 data"
  rect 1.3x1.85 smd: 1(-1.45,0)
  rrect50% 1.3x1.85 smd: 2(1.45,0)
  silkscreen extent -2.4,-1.21 2.4,1.21, body extent -1.7,-0.9 1.7,0.9, height 1.35
1206_190 [mm] "1206_190"
  rect 1.1x1.6 smd: 1(-1.7,0)
  rrect50% 1.1x1.6 smd: 2(1.7,0)
  silkscreen extent -0.9,-1 0.9,1, body extent -1.75,-0.95 1.75,0.95, height 1.9
1210#1 [mm] "1210 from SM-752 data"
  rect 1.3x2.7 smd: 1(-1.45,0)
  rrect50% 1.3x2.7 smd: 2(1.45,0)
  silkscreen extent -2.32,-1.57 2.32,1.57, body extent -1.7,-1.35 1.7,1.35, height 1.35
1210#2 [mm] "1210 from SM-752 data"
  rrect50% 1.3x2.7 smd: 1(-1.45,0)
  rect 1.3x2.7 smd: 2(1.45,0)
  silkscreen extent -2.32,-1.57 2.32,1.57, body extent -1.7,-1.35 1.7,1.35, height 1.35
1210_280 [mm] "SMD, 2-Leads, Body 3.6x2.8mm, Height 2.8mm"
  rrect50% 1.1x2.2 smd: 1(-1.65,0)
  rect 1.1x2.2 smd: 2(1.65,0)
  silkscreen extent -0.84,-1.4 0.84,1.4, body extent -1.8,-1.4 1.8,1.4, height 2.8
AssemblyNote [mil] "Assembly Note"
CKG57N#1 [mm] "Chip Capacitor, Body 6.0x5.0x5.0mm,"
  rrect50% 2x5 smd: 1(-2.95,0)
  rect 2x5 smd: 2(2.95,0)
  silkscreen extent -3.2,-2.8 3.2,2.8, body extent -3.3,-2.75 3.3,2.75, height 5.5
CKG57N#2 [mm] "Chip Capacitor, Body 6.0x5.0x5.0mm,"
  rect 2x5 smd: 1(-2.95,0) 2(2.95,0)
  silkscreen extent -3.2,-2.8 3.2,2.8, body extent -3.3,-2.75 3.3,2.75, height 5.5
CONN_131-3701-261 [mil] "Header, 2.54mm, 2x1, TH"
  round 72 hole 46: 1(0,0)
  round 92 hole 67 mask+2: 2(-100,100) 3(-100,-100) 4(100,-100) 5(100,100)
  silkscreen extent -146,-144 144,144, body extent -118,-118 118,118, height 304
CONN_CUI-PJ-202AH [mm] "Conn_DC Jack"
  rrect50% 1.5x4 hole 1 slot 3.5 at 90 deg: 1(0,0)
  oval 1.5x4 hole 1 slot 3.5 at 90 deg: 2(6,0)
  oval 4x1.5 hole 1 slot 3.5 at 0 deg: 3(3,4.7)
  silkscreen extent -0.7,-4.5 7.07,4.5, body extent -0.7,-4.5 13.7,4.9, height 11.02
CONN_TE_292303-4 [mm] "TE Connectivity"
  round 1.524 hole 0.92: 1(-3.5,0) 2(-1,0) 3(1,0) 4(3.5,0)
  round 3 hole 2.3: 5(-6.57,-2.71) 6(6.57,-2.71)
  silkscreen extent -7.32,-12.99 7.3,1.01, body extent -8.12,-12.99 8.12,1.01, height 7.67
CONN_USB_896-43-004-00-000000 [mm] "MILLMAX"
  rrect50% 1.12x2.87 smd: 1(-3.49,1.768)
  rect 1.12x2.87 smd: 2(-1,1.768) 3(1,1.768) 4(3.49,1.768)
  round 3.17 hole 2.3 slot 2.5 at 90 deg: 5(-6.565,-1.767) 6(6.565,-1.767)
  silkscreen extent -6.55,-5.56 6.55,1.93, body extent -6.55,-12.07 6.55,1.92, height 6.99
DAR70510#1 [mil] "RELAY REED SPST 3A 5V"
  round 80 hole 45: 1(0,0) 3(1000,200) 4(1000,-200)
  rect 80x80 hole 45: 2(2000,0)
  silkscreen extent -180,-310 2180,310
DAR70510#2 [mil] "RELAY REED SPST 3A 5V"
  round 80 hole 45: 1(0,0) 2(2000,0) 3(1000,200) 4(1000,-200)
  silkscreen extent -180,-310 2180,310
DBQ0016A_N [mm] "SOP, 16-Leads, Body 4.9x3.9mm, Pitch 0.635mm, IPC Medium Density"
  rrect50% 1.45x0.4 smd: 1(-2.725,2.222) 2(-2.725,1.587) 3(-2.725,0.953) 4(-2.725,0.318) 5(-2.725,-0.318) 6(-2.725,-0.953) 7(-2.725,-1.587) 8(-2.725,-2.222) 9(2.725,-2.222) 10(2.725,-1.587) 11(2.725,-0.953) 12(2.725,-0.318) 13(2.725,0.318) 14(2.725,0.953) 15(2.725,1.587) 16(2.725,2.222)
  silkscreen extent -3.35,-2.5 1.1,2.68, body extent -3.01,-2.45 3.01,2.45, height 1.63
DCK0005A_N [mm] "SOT353, 5-Leads, Body 2x1.3mm, Pitch 0.65mm, Lead Span 2.1mm, IPC Medium Density"
  rrect25% 0.85x0.4 smd: 1(-1.125,0.65) 2(-1.125,0) 4(1.125,-0.65) 5(1.125,0.65)
  rect 0.85x0.4 smd: 3(-1.125,-0.65)
  silkscreen extent -1.48,-1.02 0.55,1.1, body extent -1.14,-1 1.14,1, height 0.95
DCQ0006A_N [mm] "SOT223, 6-Leads, Body 6.6x7.3mm (max), Pitch 1.27mm, IPC Medium Density"
  rrect17% 2.1x0.6 smd: 1(-2.975,2.54) 2(-2.975,1.27) 3(-2.975,0) 4(-2.975,-1.27) 5(-2.975,-2.54)
  rect 2.1x3.2 smd: 6(2.975,0)
  silkscreen extent -1.5,-3.27 1.5,3.27, body extent -3.54,-3.25 3.54,3.25, height 1.8
DDA0008E_N [mm]
  rrect50% 1.45x0.6 smd: 1(-2.725,1.905) 2(-2.725,0.635) 3(-2.725,-0.635) 4(-2.725,-1.905) 5(2.725,-1.905) 6(2.725,-0.635) 7(2.725,0.635) 8(2.725,1.905)
  rrect4% 2.4x3.1 smd: 9(0,0)
  silkscreen extent -3.22,-2.5 1.15,2.5, body extent -3.01,-2.45 3.01,2.45, height 1.7
DPY0002A [mm] "R-PX2SON-N2"
  rect 0.6x0.5 smd: 1(-0.5,0) 2(0.5,0)
  body extent -0.55,-0.35 0.55,0.35, height 0.4
EKMH350VSN223MA50T [mil] "CAP ALUM 22000UF 20% 35V SNAP"
  round 110 hole 80: 1(0,0) 2(393.7,0)
  silkscreen extent -590,-689 984,689
Fiducial10-20 [mm]
  round 1 smd mask+0.5: 1(0,0)
  Top Layer keep-out circle w1.178: c0,0 r0.5
GPB527C202BR [mm] "SWITCH PUSH SPST-NO 10A 125V"
  rrect50% 1.6x5.6 hole 1 slot 5 at 90 deg: 1(-4,4.5) 2(-4,-4.5)
  silkscreen extent -11.5,-11.5 11.5,11.5
Harwin_R30-3000502 [mil] "HEX STANDOFF M3 BRASS 5MM"
  body extent -114,-98 114,98, height 486
Keystone5000 [mil] "For Keystone 500x miniature loop terminals"
  round 80 hole 40: 1(0,0)
  silkscreen extent -58,-58 58,58, body extent -49,-49 49,49, height 182
Keystone29311#1 [mm] "Srcew, Pan HeadM5x0.5 mm, Zinc Plated  6.0mm L"
  round 7 / inner round 4.9 / far side round 7 hole 3.7: 1(0,0)
  body extent -2.7,-2.7 2.7,2.7, height 1.72
Keystone29311#2 [mm] "Srcew, Pan HeadM5x0.5 mm, Zinc Plated  6.0mm L"
  round 7 / inner round 4.9 / far side round 7 hole 3.7 unplated: 1(0,0)
  body extent -2.7,-2.7 2.7,2.7, height 1.72
KSR [mm] "C&K Components SPST switch"
  rect 1.5x1.4 smd: 1(-3.25,0) 2(3.25,0)
  silkscreen extent -3.2,-2 3.2,2, body extent -3,-1.9 3,1.9, height 2.65
LED_LTST-C171 [mm] "LITE-ON"
  rect 1.2x1.2 smd: 1(-1.05,0) 2(1.05,0)
  silkscreen extent -1.6,-1 2.2,1, body extent -1.05,-0.67 1.05,0.67, height 0.8
Mill-Max_800-10-002-10-001000 [mm] "Mill-Max"
  rect 1.5x1.5 hole 0.85: 1(-1.27,0)
  round 1.5 hole 0.85: 2(1.27,0)
  silkscreen extent -2.54,-1.27 2.54,1.78, body extent -2.54,-1.27 2.54,1.27, height 8.13
Molex_22-23-2021 [mm] "Header, 2.54mm, 2x1, TH"
  rrect6% 1.55x1.55 hole 1.02: 1(-1.27,0)
  round 1.55 hole 1.02: 2(1.27,0)
  silkscreen extent -2.92,-3.25 2.46,3.1, body extent -2.46,-3.25 2.46,3.1, height 10.08
MOLEX_67068-8000 [mm] "MOLEX"
  rect 1.524x1.524 hole 0.914: 1(-4.71,1.25)
  round 1.524 hole 0.914: 2(-4.71,-1.25) 3(-2.71,-1.25) 4(-2.71,1.25)
  round 3.5 hole 2.3: 5(0,6.02) 6(0,-6.02)
  silkscreen extent -6.72,-5.75 3.65,5.75, body extent -6.72,-7.43 10.28,7.43, height 11.02
Pb-Free_Overlay_Small [mil]
  silkscreen extent -46,-46 46,46
PHP0048C_N [mm] "Thin QFP, 48-Leads, Body 7x7mm, Pitch 0.5mm, Thermal Pad 3x3mm, IPC Medium Density"
  rrect100% 1.45x0.3 smd mask+0.047: 1(-4.225,2.75) 2(-4.225,2.25) 3(-4.225,1.75) 4(-4.225,1.25) 5(-4.225,0.75) 6(-4.225,0.25) 7(-4.225,-0.25) 8(-4.225,-0.75) 9(-4.225,-1.25) 10(-4.225,-1.75) 11(-4.225,-2.25) 12(-4.225,-2.75) 25(4.225,-2.75) 26(4.225,-2.25) 27(4.225,-1.75) 28(4.225,-1.25) 29(4.225,-0.75) 30(4.225,-0.25) 31(4.225,0.25) 32(4.225,0.75) 33(4.225,1.25) 34(4.225,1.75) 35(4.225,2.25) 36(4.225,2.75)
  rrect100% 0.3x1.45 smd mask+0.047: 13(-2.75,-4.225) 14(-2.25,-4.225) 15(-1.75,-4.225) 16(-1.25,-4.225) 17(-0.75,-4.225) 18(-0.25,-4.225) 19(0.25,-4.225) 20(0.75,-4.225) 21(1.25,-4.225) 22(1.75,-4.225) 23(2.25,-4.225) 24(2.75,-4.225) 37(2.75,4.225) 38(2.25,4.225) 39(1.75,4.225) 40(1.25,4.225) 41(0.75,4.225) 42(0.25,4.225) 43(-0.25,4.225) 44(-0.75,4.225) 45(-1.25,4.225) 46(-1.75,4.225) 47(-2.25,4.225) 48(-2.75,4.225)
  rrect2% 4.6x4.6 smd: 49(0,0)
  silkscreen extent -4.39,3.15 -4.14,3.4, body extent -4.51,-4.51 4.51,4.51, height 1.2
PowerDI5 [mm] "Diodes Inc recommended land pattern, ap02001.pdf rev 60"
  rect 1.4x1.39 smd: 1(-1.991,0.92) 2(-1.991,-0.92)
  rrect50% 4.86x3.36 smd: 3(1.991,0)
  silkscreen extent -1.7,-2.1 3.8,2.1, body extent -2.27,-2.03 4.33,2.03, height 1.17
RGW0020A [mm] "QFN, 20-Leads, Body 5x5mm, Pitch 0.65mm, Thermal Pad 3.15x3.15mm, TI Recommended"
  rrect50% 0.75x0.3 smd: 1(-2.325,1.3) 2(-2.325,0.65) 3(-2.325,0) 4(-2.325,-0.65) 5(-2.325,-1.3) 11(2.325,-1.3) 12(2.325,-0.65) 13(2.325,0) 14(2.325,0.65) 15(2.325,1.3)
  rrect50% 0.3x0.75 smd: 6(-1.3,-2.325) 7(-0.65,-2.325) 8(0,-2.325) 9(0.65,-2.325) 10(1.3,-2.325) 16(1.3,2.325) 17(0.65,2.325) 18(0,2.325) 19(-0.65,2.325) 20(-1.3,2.325)
  rrect50% 3.15x3.15 smd paste-1.575: 21(0,0)
  silkscreen extent -2.73,-2.73 2.73,2.73, body extent -2.58,-2.57 2.57,2.58, height 1.01
SMA [mm] "Molded Diode, 2-Leads, Body 4.3x2.6mm, IPC Medium Density, based on OnSemi component dimensions and land pattern"
  rect 2x2 smd: 1(-2,0) 2(2,0)
  silkscreen extent -3.66,-1.57 2.79,1.57, body extent -2.6,-1.3 2.6,1.3, height 2.42
SOIC-8 [mm] "duplicate of SO-8.  SOIC, 8-Leads, Body 5.0x4.0mm (max), Pitch 1.27mm, IPC Medium Density"
  rrect17% 1.45x0.6 smd: 1(-2.725,1.905) 2(-2.725,0.635) 3(-2.725,-0.635) 4(-2.725,-1.905) 5(2.725,-1.905) 6(2.725,-0.635) 7(2.725,0.635) 8(2.725,1.905)
  silkscreen extent -3.5,-2.5 0.9,2.5, body extent -3,-2.45 3,2.45, height 1.63
TEH100M7R50FE [mil] "100W Resistor"
  round 100 hole 70: 1(0,0) 2(400,0)
Tek_131-5031-00 [mil] "Tektronix cold nose probe"
  rect 25x25 smd: 1(0,0)
  round 60 hole 38: 2(-100,100) 3(-100,-100) 4(100,-100) 5(100,100)
  body extent -206,-206 206,206, height 351
TI_Horizontal_Overlay_Medium [mil]
  silkscreen extent -750,-94 750,94
VLMx1500_Red#1 [mm] "Vishay"
  rect 0.6x0.7 smd: 1(-0.475,0) 2(0.475,0)
  silkscreen extent 0.92,-0.32 1.12,0.33, body extent -0.6,-0.35 0.6,0.35, height 0.56
VLMx1500_Red#2 [mm] "Vishay"
  rrect50% 0.6x0.7 smd: 1(-0.475,0)
  rect 0.6x0.7 smd: 2(0.475,0)
  silkscreen extent 0.92,-0.32 1.12,0.33, body extent -0.6,-0.35 0.6,0.35, height 0.56
WE-HCI_7050 [mm] "Wurth Electronik recommended land pattern"
  rect 2.7x2.2 smd: 1(-2.55,0) 2(2.55,0)
  silkscreen extent -3.7,-3.7 3.7,3.7, body extent -3.6,-3.6 3.6,3.6, height 5
WURTH_61300111121 [mm] "Header, 2.54 mm, 1x1, TH"
  rect 1.65x1.65 hole 1.15: 1(0,0)
  silkscreen extent -1.27,-1.27 1.27,1.27, body extent -1.27,-1.27 1.27,1.27, height 8.54

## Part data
C1: library part EMVA6R3GTR103MMN0S, "CAP, AL, 10000 µF, 6.3 V, +/- 20%, SMD"
C2: "CAP, CERM, 0.1 µF, 16 V, +/- 10%, X7R, 0603"
C3 C11 C17 C22: "CAP, CERM, 10 µF, 16 V, +/- 20%, X5R, 0805"
C4 C5: "CAP, CERM, 4.7 µF, 50 V, +/- 10%, X7R, 1210"
C6: "CAP, CERM, 0.22 µF, 50 V, +/- 10%, X7R, 0805"
C7: "CAP, CERM, 1 µF, 25 V, +/- 10%, X7R, 0805"
C8 C9: "CAP, CERM, 47 µF, 16 V, +/- 20%, X5R, 1210"
C10: "CAP, CERM, 0.022 µF, 16 V, +/- 10%, X7R, 0402"
C12: "CAP, CERM, 1 µF, 6.3 V, +/- 20%, X7R, 0402"
C13 C14: "CAP, CERM, 20 pF, 50 V, +/- 5%, C0G/NP0, 0402"
C15: library part 12063C564KAT2A, "CAP, CERM, 0.56 µF, 25 V, +/- 10%, X7R, 1206"
C16 C18: "CAP, CERM, 1000 pF, 2000 V, +/- 10%, X7R, 1206_190"
C19 C20 C24 C26 C30 C31 C32 C33: "CAP, CERM, 0.01 µF, 50 V, +/- 10%, X7R, 0402"
C21 C23 C25 C27 C34 C35: "CAP, CERM, 0.1 µF, 25 V, +/- 20%, X7R, 0402"
C28 C29: "CAP, CERM, 1 µF, 50 V, +/- 10%, X7R, 0603"
C36 C43: "CAP, CERM, 10 µF, 100 V, +/- 20%, X7R, 6x5x5mm"
C37 C38 C41: "CAP, CERM, 100 µF, 10 V, +/- 20%, X5R, 1210"
C39 C40 C42: "CAP, CERM, 10 µF, 6.3 V, +/- 20%, X7R, 0805"
C47 C49: "CAP, CERM, 0.1 µF, 25 V, +/- 5%, X7R, 0603"
C48 C50: "CAP, CERM, 1000 pF, 25 V, +/- 10%, X7R, 0402"
C51: "CAP, CERM, 2.2 µF, 6.3 V, +/- 20%, X5R, 0402"
D1 D3 D7: "LED, Green, SMD"
D2: "Diode, Schottky, 60 V, 5 A, PowerDI5"
D8 D9 D10 D12 D13 D14 D15: "LED, Super Red, SMD"
D11: "Diode, Zener, 15 V, 500 mW, SMA"
FID1 FID2 FID3: "Fiducial mark.  There is nothing to buy or mount."
H1 H2 H3 H4: "Screw Pan Head M3"
H5 H6 H7 H8: "HEX STANDOFF M3 BRASS 5MM"
J1: "Connector, DC Jack 2.1X5.5 mm, TH"
J2 J16 J17: "Connector, SMB,Vertical RCP 0-4GHz, 50 ohm, TH"
J3 J4 J11 J12: "Compact Probe Tip Circuit Board Test Points, TH, 25 per"
J5: "Connector, Receptacle, USB Type A, R/A, Top Mount TH"
J6: "Connector, Receptacle, USB TYPE B, R/A, Top Mount TH"
J7: "Connector, Receptacle, USB TYPE A, 4POS SMD"
J8 J10: "Header, 100mil, 2x1, TH"
J13 J14: "Header, 2.54mm, 2x1, Vertical, TH"
J15 J18: "Header, 2.54 mm, 1x1, Gold, TH"
L1: "Inductor, Shielded Drum Core, Superflux, 6.5 µH, 6 A, 0.0225 ohm, SMD"
Logo1: library part TI_Logo, "Texas Instrument Corporate Signature"
Logo2: library part Pb-Free
R1: "RES, 825, 1%, 0.063 W, 0402"
R2: "RES, 100 k, 0.5%, 0.063 W, 0402"
R3 R30: "RES, 255, 1%, 0.063 W, 0402"
R4: library part SQP10AJB-7R5, "RES, 7.5, 5%, 10 W, RES 48x9.5x9mm"
R5: "RES, 17.8 k, 1%, 0.063 W, 0402"
R6: "RES, 49.9 k, 1%, 0.063 W, 0402"
R7: "RES, 30.1 k, 1%, 0.063 W, 0402"
R8: "RES, 1.00 M, 1%, 0.063 W, 0402"
R12: "RES, 1.87 k, 1%, 0.063 W, 0402"
R13 R14: "RES, 30.1, 1%, 0.063 W, 0402"
R15: "RES, 330, 5%, 0.063 W, 0402"
R16: "RES, 4.99 k, 1%, 0.063 W, 0402"
R17: "RES, 9.53 k, 1%, 0.063 W, 0402"
R18: "RES, 1.00 k, 1%, 0.063 W, 0402"
R19 R20 R21: "RES, 4.7 k, 5%, 0.063 W, 0402"
R22 R23 R26: "RES, 10.0k ohm, 1%, 0.1W, 0603"
R24: "RES, 90.9 k, 1%, 0.063 W, 0402"
R25: "RES, 10.0 k, 0.5%, 0.063 W, 0402"
R27 R28 R31: "RES, 165, 1%, 0.063 W, 0402"
S1: "SWITCH PUSH SPST-NO 10A 125V"
S2 S3: "Switch, Normally open, 2.3N force, 200k operations, SMD"
TP1: "Test Point, Miniature, Red, TH"
U1 U2 U3: "AUTOMOTIVE USB 2.0 Interface Protection with Short-to-Battery and Short-to-Ground Protection, DBQ0016A"
U4: library part TSB41AB1PHPG4, "400 Mbps IEEE 1394a One-Port Cable Transceiver / Arbiter, 3.3V, 0 to 70 degC, 48-Pin HTQFP (PHP), Green (RoHS & no Sb/Br)"
U5: "SIMPLE SWITCHER 40 V 3.5 A, 2.2 MHz Step-Down Converter with 40 µA IQ, DDA0008E"
U6: "Single Output Fast Transient Response LDO, 1.5 A, Fixed 3.3 V Output, 2.1 to 20 V Input, 6-pin SOT-223 (DCQ), -40 to 125 degC, Green (RoHS & no Sb/Br)"
U7: "Single Output LDO, 1.5 A, Adjustable 0.8 to 3.6 V Output, 0.8 to 5.5 V Input, with Programmable Soft Start, 20-pin VQFN (RGW), -40 to 125 degC, Green (RoHS & no Sb/Br)"
U8 U9 U17: library part SN74LVC1G125DCKR, "Single Bus Buffer Gate With 3-State Output, DCK0005A"
U11 U12: library part ACS712ELCTR-20A-T, "Fully Integrated, Hall Effect-Based Linear Current Sensor IC with 2.1kVRMS Isolation and a Low-Resistance Current Conductor, SOIC-8"
U13 U14 U15 U16: library part TPD1E10B06DPYR, "ESD in 0402 Package with 10 pF Capacitance and 6 V Breakdown, 1 Channel, -40 to +125 degC, 2-pin X2SON (DPY), Green (RoHS & no Sb/Br)"
Y1: library part ECS-240-20-5PX-TR, "Crystal, 24.000MHz, 20pF, SMD"
ZZ1 ZZ2 ZZ3: library part AssemblyNote

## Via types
v1: diameter 19.68, hole 7.87, Top Layer to Bottom Layer, tented both sides, 170 vias
v2: diameter 34, hole 16, Top Layer to Bottom Layer, tented both sides, 91 vias

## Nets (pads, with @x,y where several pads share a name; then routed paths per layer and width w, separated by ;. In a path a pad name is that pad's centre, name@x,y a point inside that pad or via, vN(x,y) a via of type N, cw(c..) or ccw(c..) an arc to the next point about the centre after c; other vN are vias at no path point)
+1P1: C17.1 C30.2 C31.2 C32.2 C33.2 C34.2 C35.2 R12.2 U4.1 U4.12 U4.18 U4.30 U4.34 U4.45 U7.1 U7.18 U7.19 U7.20 | length 744.6
  Top Layer w10: C35.2@4771.79,1078.16 U4.1@4862.26,1078.16 4899.84,1078.16 v1(4909.49,1068.51) ; U4.12@4862.26,861.63 4899.84,861.63 v1(4909.49,871.27) ; C30.2@4978.6,1195.58 4979.38,1194.79 U4.45@4979.38,1136.23 v1(4979.38,1089.05) ; C33.2@5018.75,723.52 U4.18@5018.75,803.55 ; v1@5147.7,1048.44 5157.35,1038.79 U4.34@5194.93,1038.79 5231.01,1038.79 5244.17,1051.95 C31.2@5274.23,1051.95 ; v1(5147.75,960.05) U4.30@5194.93,960.05 5229.39,960.05 5240.39,949.05 C32.2@5274.23,949.05
  Top Layer w18: v1(4987.19,723.52) C33.2@5018.75,723.52
  Layer 3 w4: 5128.22,1028.01 v1(5147.7,1047.49)
  Layer 3 w5: 5128.2,989.3 5128.22,1028.01
  other v1: 4856.8,840 4817.03,1078.16 4796.8,1920 4836.8,1920 4876.8,1920 4796.8,1950 4836.8,1950 4876.8,1950
+3P3: C11.1 C19.2 C20.2 C21.2 C23.2 C24.2 C25.2 C26.2 C27.2 C39.1 C40.1 C42.1 D7.1 R22.2 R23.1 R26.2 U1.9 U2.9 U3.9 U4.7 U4.13 U4.23 U4.25 U4.33 U4.37 U4.40 U4.48 U6.4 U6.5 U8.2 U8.5 U9.2 U9.5 U17.2 U17.5 | length 1875.5
  Top Layer w6: v1(912.26,800) 944.93,800 954.93,790 U17.2@1035.84,790 1070.13,790 1095.72,815.59 U17.5@1124.42,815.59 ; U8.5@3340.84,1726.27 3340.84,1695.61 3366.43,1670.02 U8.2@3366.43,1637.69 3366.43,1606.74 3374.89,1598.28 R22.2@3374.89,1567.05 ; v1(4352.46,875.21) 4352.46,909.66 4387.8,945 U9.2@4387.8,1051.25 4387.8,1082 4362.21,1107.59 U9.5@4362.21,1139.84
  Top Layer w10: C26.2@4771.79,999.89 4791.9,999.89 4831.75,960.05 U4.7@4862.26,960.05 4909.44,960.05 v1(4909.49,960) ; C25.2@4903.79,723.52 4903.84,723.56 4903.84,749.29 4919.25,764.71 4919.25,765.47 4920.33,766.54 U4.13@4920.33,803.55 4920.33,841.14 v1(4929.97,850.79) ; U4.48@4920.33,1136.23 4920.33,1098.65 v1(4929.97,1089) ; U4.40@5077.81,1136.23 C20.2@5077.8,1220.38 ; C24.2@5117.18,723.52 U4.23@5117.18,803.55 5117.18,833.35 5145.45,861.63 U4.25@5194.93,861.63 v1(5242.11,861.63) ; v1@5147.7,1009.46 5157.35,1019.11 U4.33@5194.93,1019.11 5231.03,1019.11 5249.09,1001.05 C27.2@5274.23,1001.05 ; U6.5@5267.85,1776.5 5267.85,1728.32 5288.36,1707.82 5354.22,1707.82 5386.17,1675.86 D7.1@5417.11,1675.86
  Top Layer w15: v1(912.26,800) 912.8,800.54 R23.1@912.8,848.5
  Top Layer w16: v1(5045.8,1245) 5070.42,1220.38 C20.2@5077.8,1220.38
  Top Layer w18: C26.2@4771.79,999.89 v1(4771.8,1031.45) ; v1(4872.24,721.53) C25.2@4903.79,721.53
  other v1: 4754.52,704.3 4794.52,704.3 4754.52,734.3 4794.52,734.3 5203.67,821.08 4304.8,841 4338.53,840.61 5186.25,840.45 838.8,968 861.8,989 5147.7,1008.51 5180.08,1127.24 4901.3,1128.06 5159.92,1143 4880.52,1143.7 3371.8,1504 3406.8,1504 3406.8,1534 5166.8,1710 5206.8,1710 5246.8,1710 5166.8,1740 5206.8,1740 5246.8,1740
+5V: C3.1 C7.1 C8.1 C9.1 C22.1 C37.1 C38.1 C41.1 C47.1 C49.1 J2.1 J13.1 J14.1 L1.2 R2.1 R3.1 R13.2 R14.2 S2.2 S3.2 U1.14 U1.15 U2.14 U2.15 U3.14 U3.15 U6.2 U7.5 U7.6 U7.7 U7.8 U7.10 U11.8 U12.8 | length 6224.7
  Top Layer w10.5: C22.1@4408.96,1909.39 C22.1@4409.37,1908.98 ; R14.2@4427.94,1832.01 4428.14,1832.2 U7.10@4480.42,1832.2
  Top Layer w12: C9.1@4360.7,2314.86 4330.41,2314.86 4267.67,2377.6 4267.67,2477.17 4294.61,2504.11 R2.1@4661.17,2504.11 R3.1@4661.17,2602.39
  Top Layer w16: 83.22,1073 83.22,900 ; 84.52,799.44 J13.1@239.65,799.44 ; 84.87,901.65 83.22,900 ; v1(706.8,707.89) 132.05,707.89 83.22,756.72 83.22,900 ; v1(3734.02,530.14) 4092.3,530.14 v1(4215.01,407.43)
  Top Layer w20: 83.22,1073 S2.2@166.84,1073 ; 83.22,2000 S3.2@166.84,2000 ; 83.22,2350 J14.1@244.8,2350 ; 5189.67,1926.5 U6.2@5267.85,1926.5
  Top Layer w86.61: C7.1@4462.55,2271 L1.2@4597.4,2271
  Bottom Layer w12: C49.1@4264.08,409.61 C49.1@4266.26,407.43
  Bottom Layer w16: v1(706.8,707.89) U11.8@796.92,707.89 876.34,707.89 C47.1@876.5,707.73 916.67,707.73 1140.4,484 3687.87,484 v1(3734.02,530.14) ; v1(4215.01,407.43) C49.1@4266.26,407.43
  Bottom Layer w20: C49.1@4264.08,409.61 U12.8@4264.08,475
  other v1: 1016.8,890 1046.8,890 1016.8,940 1046.8,940 4276.8,1060 4306.8,1060 4306.8,1100 99.94,1359.48 134.94,1359.48 99.94,1409.48 134.94,1409.48 3260.23,1650 3290.23,1650 3290.23,1690 4346.8,1830 4386.8,1830 4346.8,1860 4386.8,1860 4346.8,1900 5086.8,1940 5126.8,1940 5176.8,1940 4456.8,2073.33 4486.8,2073.33 4516.8,2073.33 4456.8,2113.33 4486.8,2113.33 4516.8,2113.33 4456.8,2153.33 4486.8,2153.33 4516.8,2153.33 4456.8,2203.33 4486.8,2203.33 4516.8,2203.33
+18V: C4.2 C5.2 C6.2 C43.1 J1.1 R1.2 R4.1 U5.2 U5.3 | length 162.3
  Top Layer w12: C6.2@5284.28,2358.49 C6.2@5284.8,2359 ; 5284.8,2420 R1.2@5284.8,2485.38
  Top Layer w22: U5.2@5188.07,2358.49 C6.2@5284.28,2358.49
DP1_CON_N: J5.2 U3.7 U13.1 | length 971.3
  Top Layer w6.25: J5.2@793.57,306.19 793.57,373.18 759.32,407.43 759.32,931.06 759.32,954.6 cw(c803.89,954.6) 772.38,986.11 789.02,1002.75 888.88,1102.62 ccw(c850.13,1141.37) 904.93,1141.37 904.93,1164.91 912.31,1172.29 U3.7@912.31,1204.21
DP1_CON_P: J5.3 U3.8 U14.1 | length 971.3
  Top Layer w6.25: J5.3@714.83,306.19 714.83,373.18 749.08,407.43 749.08,954.6 cw(c803.89,954.6) 765.13,993.35 781.78,1010 865,1093.22 881.64,1109.86 ccw(c850.13,1141.37) 894.69,1141.37 894.69,1164.91 887.31,1172.29 U3.8@887.31,1204.21
DP1_STB_N: J11.1 K2.2 U2.6 U3.5 | length 2390.9
  Top Layer w6.24: 954.93,1492.73 cw(c1032.2,1492.73) 1032.2,1570 2064.2,1570
  Top Layer w6.25: 954.93,1492.73 954.93,1243.52 962.31,1236.13 U3.5@962.31,1204.21 ; 2064.2,1570 2967.8,1570 2975.19,1562.61 U2.6@3007.11,1562.61
DP1_STB_P: J12.1 K3.2 U2.5 U3.6 | length 2407
  Top Layer w6.24: 944.69,1492.73 cw(c1032.2,1492.73) 1032.2,1580.24 2064.2,1580.24 cw(c2064.2,1570) 2064.54,1580.24
  Top Layer w6.25: U3.6@937.31,1204.21 937.31,1236.13 944.69,1243.51 944.69,1492.73 ; 2064.54,1580.24 2967.8,1580.24 2975.19,1587.61 U2.5@3007.11,1587.61
DP1_STB_VBUS: C29.1 D11.1 S1.2 TP1.1 U2.2 U2.3 | length 833.9
  Top Layer w60: S1.2@3668.44,3322.83 3978.33,3322.83 4102.65,3447.15 D11.1@4450.87,3447.15
  other v1: 2902.8,1645.86 2942.8,1645.86 2902.8,1675.86 2942.8,1675.86
DP1_SYS_N: J3.1 U2.8 U4.42 | length 2231.5
  Top Layer w6.24: U2.8@3007.11,1512.61 3039.03,1512.61 3046.41,1519.99 3069.95,1519.99 cw(c3069.95,1475.42) 3101.46,1506.94 3118.1,1490.29 3201.32,1407.07 3217.97,1390.43 ; 3256.72,1374.38 3432.55,1374.38 4854.11,1374.38 cw(c4854.11,1329.82) 4885.62,1361.33 4917.14,1329.81 4933.78,1313.16 4965.3,1281.65 4981.94,1265 5013.46,1233.48 5030.11,1216.84 cw(c4998.59,1185.33) 5043.16,1185.33 5043.16,1171.95 5038.44,1167.23 U4.42@5038.44,1136.23
  Top Layer w6.25: 3217.97,1390.43 ccw(c3256.72,1429.19) 3256.72,1374.38
DP1_SYS_P: J4.1 U2.7 U4.41 | length 2247.6
  Top Layer w6.24: U2.7@3007.11,1537.61 3039.03,1537.61 3046.41,1530.23 3069.95,1530.23 cw(c3069.95,1475.42) 3108.7,1514.18 3208.57,1414.31 3225.21,1397.67 ; 3256.72,1384.62 4854.11,1384.62 cw(c4854.11,1329.82) 4892.86,1368.57 4924.38,1337.05 4941.02,1320.41 4972.54,1288.89 4989.18,1272.24 5020.7,1240.72 5037.35,1224.08 cw(c4998.59,1185.33) 5053.4,1185.33 5053.4,1171.95 5058.12,1167.23 U4.41@5058.12,1136.23
  Top Layer w6.25: 3225.21,1397.67 ccw(c3256.72,1429.19) 3256.72,1384.62
DP2_CON_N: J7.2 J10.2 U1.6 | length 801.1
  Top Layer w6.24: 3881.04,906.85 3881.04,837.9 ccw(c3942.65,837.9) 3899.09,794.33 J10.2@3925.92,767.5 ; 3881.1,906.85 cw(c3958.37,906.85) 3958.37,984.12 ; 3958.27,984.12 3981.81,984.12 3989.19,976.74 U1.6@4021.11,976.74
  Bottom Layer w6.24: J7.2@3915.29,338.67 3915.29,373.18 3881.04,407.43 3881.04,692.83 cw(c3952.96,692.83) 3902.11,743.68 J10.2@3925.92,767.5
DP2_CON_P: J7.3 J10.1 U1.5 | length 817.2
  Top Layer w6.24: J10.1@3825.92,767.5 3852.75,794.33 ccw(c3809.18,837.9) 3870.8,837.9 3870.8,906.85 ; 3870.76,906.85 cw(c3958.27,906.85) 3958.27,994.36 3981.81,994.36 3989.19,1001.74 U1.5@4021.11,1001.74
  Bottom Layer w6.24: J10.1@3825.92,767.5 3849.74,743.68 cw(c3798.89,692.83) 3870.8,692.83 3870.8,407.43 3836.55,373.18 J7.3@3836.55,338.67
